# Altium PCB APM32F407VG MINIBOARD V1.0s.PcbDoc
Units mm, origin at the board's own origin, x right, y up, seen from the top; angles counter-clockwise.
Board outline 442.79 x 366.46 mm, 2 copper layers (Top Layer, Bottom Layer); 85 components, 122 nets, 428 pads, 246 vias.
Unrouted connection lines stored in the file: 122.
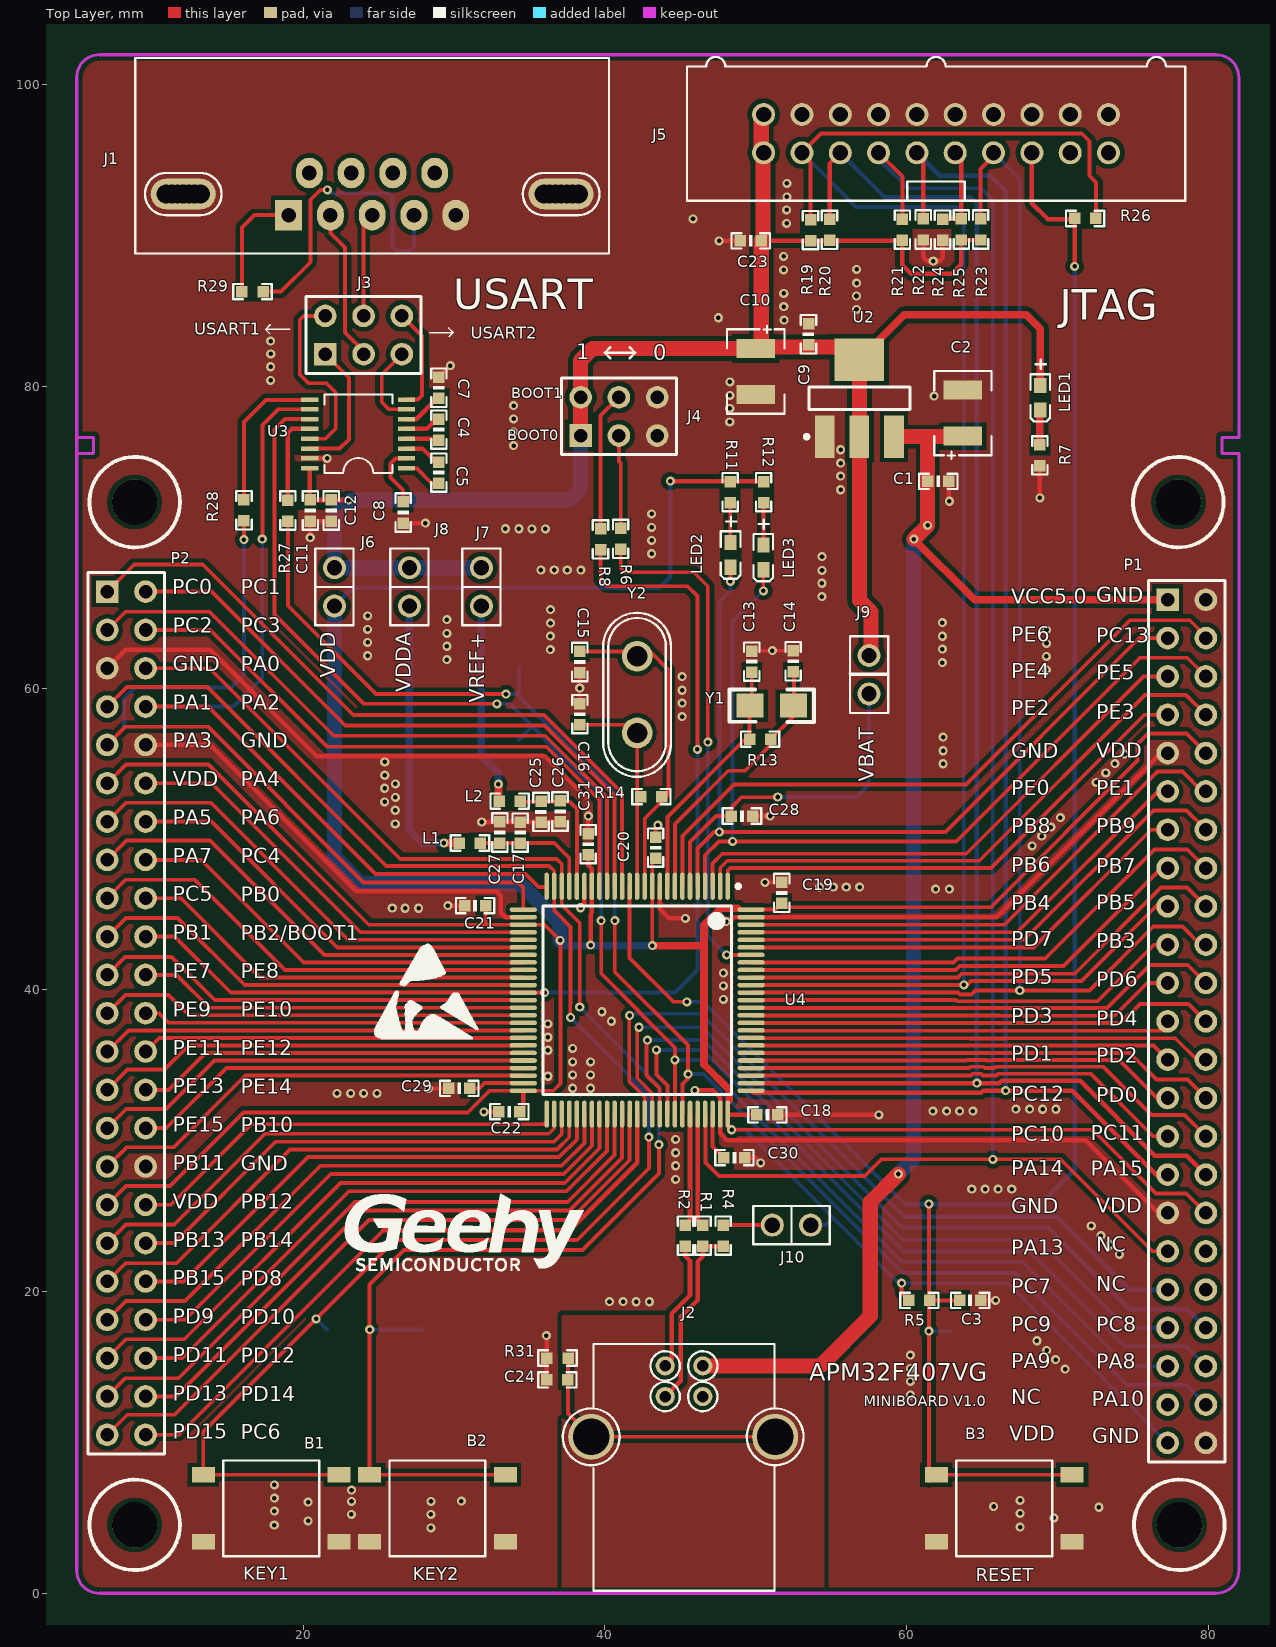
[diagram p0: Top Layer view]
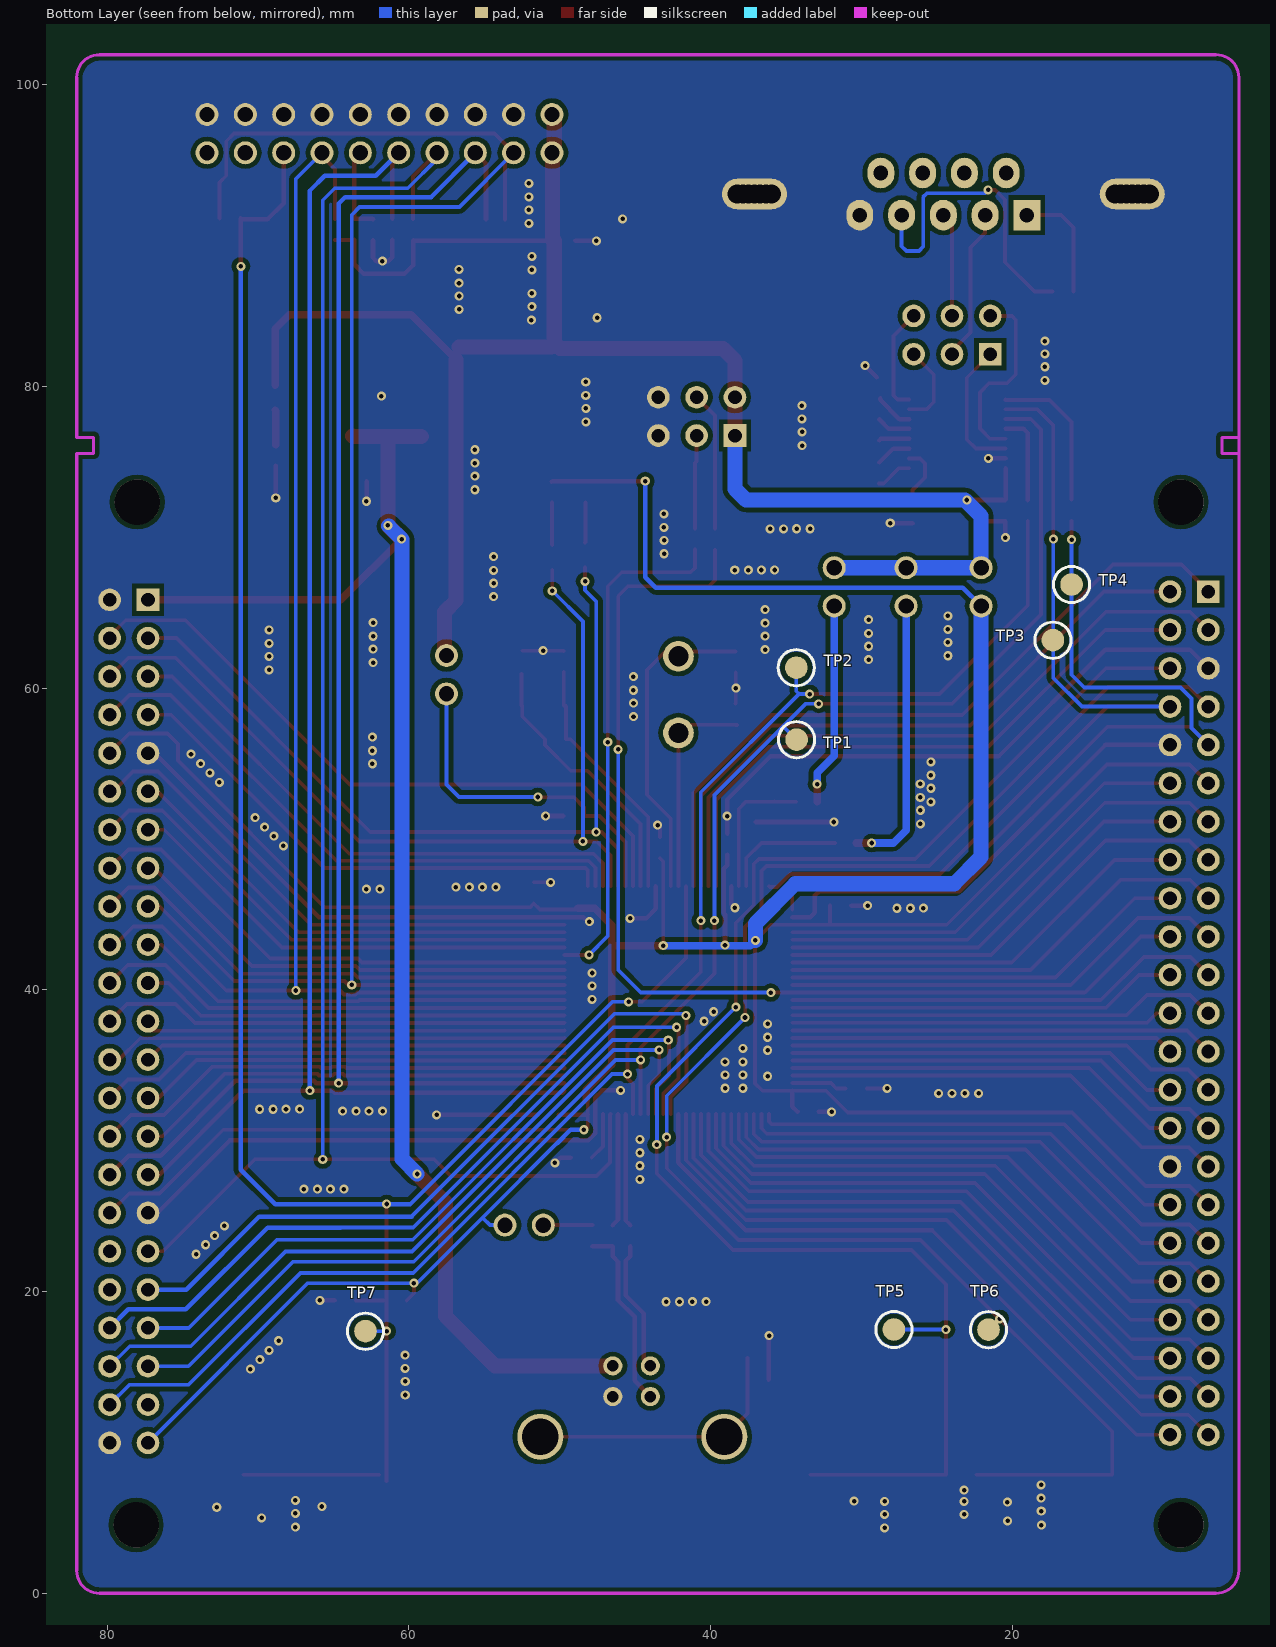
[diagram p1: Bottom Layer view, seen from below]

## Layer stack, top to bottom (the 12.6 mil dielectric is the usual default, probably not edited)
Top Layer: signal copper 0.0356
Dielectric: dielectric 0.32, FR-4, Dk 4.8
Bottom Layer: signal copper 0.0356

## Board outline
-118.26,-92.445 324.36,-92.445 324.36,273.475 323.99,273.845 323.82,274.015 -118.43,274.015

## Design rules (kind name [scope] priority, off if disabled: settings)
Clearance Clearance_1 [IsRegion] p1: gap=0.3
Clearance [All] p2: gap=0.2
ComponentClearance [All] p1: gap=0 collisioncheckmode=3 verticalgap=0.1 showdistances=FALSE
PolygonConnect [All] p1: connectstyle=Direct reliefconductorwidth=0.254 reliefentries=4 polygonreliefangle="45 Angle" airgapwidth=0.254
RoutingVias [All] p1: holewidth=0.3 width=0.6 viastyle="Through Hole" minholewidth=0.3 minwidth=0.6 maxholewidth=0.711 maxwidth=1.2
SilkToSolderMaskClearance SilkscreenOverComponentPads [IsPad] p1: minsilkscreentomaskgap=0.254 clearancetoexposedcopper=TRUE
SolderMaskExpansion [All] p1: expansion=0.102
Width Width_GND [InNet('GND')] p1: maxlimit=2 minlimit=0.15 preferedwidth=1
Width Width_C6-2 [InNet('NetC6_2')] p2: maxlimit=1.2 minlimit=1.2 preferedwidth=1.2
Width Width_MCU11 [InNet('MCU11')] p3: maxlimit=1.5 minlimit=0.3 preferedwidth=0.6
Width [All] p4: maxlimit=1 minlimit=0.254 preferedwidth=0.254 checkconnectedcopper=TRUE
26 further rules are at their usual default settings.

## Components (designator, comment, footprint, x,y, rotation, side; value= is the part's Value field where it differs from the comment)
B1 "Tamper" PB10 17.89,5.635 r90 top
B2 "Tamper" PB10 28.91,5.635 r90 top
B3 "Tamper" PB10 66.47,5.635 r90 top
C1 "100nF" 0603P 62.098,73.703 r180 top
C2 "220uF" TAN-B 63.73,78.22 r90 top
C3 "100nF" 0603P 64.21,19.415 r180 top
C4 "100nF" 0603P 29.003,74.282 r90 top
C5 "100nF" 0603P 29.003,77.132 r90 top
C7 "100nF" 0603P 29.003,79.904 r270 top
C8 "100nF" 0603P 26.634,71.635 r90 top
C9 "100nF" 0603P 53.5,83.45 r270 top
C10 "220uF" TAN-B 50,80.98 r270 top
C11 "100nF" 0603P 20.478,71.766 r270 top
C12 "100nF" 0603P 21.868,71.766 r90 top
C13 "10pF" 0603P 49.739,61.753 r270 top
C14 "10pF" 0603P 52.486,61.777 r270 top
C15 "20pF" 0603P 38.339,61.725 r90 top
C16 "20pF" 0603P 38.349,58.265 r270 top
C17 "10nF" 0603P 34.39,50.42 r270 top
C18 "100nF" 0603P 50.777,31.707 r180 top
C19 "100nF" 0603P 51.727,46.427 r270 top
C20 "100nF" 0603P 43.366,49.417 r270 top
C21 "100nF" 0603P 31.4,45.58 r0 top
C22 "100nF" 0603P 33.67,31.93 r0 top
C23 "100nF" 0603P 49.671,89.645 r0 top
C24 "4.7nF" 0603#1 36.153,14.155 r0 top
C25 "1uF" 0603P 35.771,51.791 r90 top
C26 "10nF" 0603P 37.031,51.821 r90 top
C27 "1uF" 0603P 33.04,50.428 r270 top
C28 "100nF" 0603P 49.091,51.52 r180 top
C29 "2.2uF" 0603P 30.351,33.47 r0 top (schematic designator C18)
C30 "2.2uF" 0603P 48.588,28.88 r180 top (schematic designator C18)
C31 "100nF" 0603P 38.9,49.649 r270 top (schematic designator C18)
J1 "DB9" DB9/F 19.046,91.345 r0 top
J2 "USB-typeB connector" USB-B 46.491,15.074 r0 top
J3 "Header 3X2" HDR2X3 21.471,82.127 r0 top (schematic designator P6)
J4 "Header 3X2" HDR2X3 38.394,76.735 r0 top (schematic designator P1)
J5 "JTAG" IDC20S 50.524,95.475 r90 top (schematic designator P4)
J6 "" SIP2 22.08,67.975 r270 top (schematic designator P9)
J7 "" SIP2 31.82,67.975 r270 top (schematic designator P10)
J8 "" SIP2 27.05,67.975 r270 top (schematic designator P8)
J9 "" SIP2 57.514,62.155 r270 top (schematic designator P2)
J10 "" SIP2 53.64,24.405 r180 top (schematic designator P7)
L1 "0R" 0603#1 31.76,49.73 r180 top
L2 "0R" 0603#1 34.387,52.5 r180 top
LED1 "LED" D0603 68.86,78.423 r90 top (schematic designator D1)
LED2 "LED" D0603 48.34,68.009 r90 top (schematic designator D2)
LED3 "LED" D0603 50.503,67.839 r90 top (schematic designator D3)
P1 "Header 25X2" HDR2X23 77.299,65.85 r270 top
P2 "Header 25X2" HDR2X23 7.02,66.39 r270 top
R1 "22R" 0603#2 46.505,23.712 r90 top
R2 "22R" 0603#2 45.346,23.712 r90 top
R4 "1.5K" 0603#2 47.846,23.712 r90 top
R5 "10K" 0603#2 60.841,19.415 r0 top
R6 "10K" 0603#2 41.053,69.887 r90 top
R7 "1.5K" 0603#2 68.83,75.42 r90 top
R8 "10K" 0603#2 39.715,69.855 r270 top
R11 "1.5K" 0603#2 50.523,72.986 r270 top
R12 "1.5K" 0603#2 48.31,72.986 r270 top
R13 "NC" 0603#2 50.29,56.61 r180 top
R14 "NC" 0603#2 43.08,52.8 r0 top
R19 "10K" 0603#2 53.634,90.355 r270 top
R20 "10K" 0603#2 54.894,90.375 r270 top
R21 "10K" 0603#2 59.724,90.385 r270 top
R22 "10K" 0603#2 61.104,90.395 r90 top
R23 "10K" 0603#2 64.904,90.395 r270 top
R24 "10K" 0603#2 62.384,90.385 r90 top
R25 "10K" 0603#2 63.634,90.395 r270 top
R26 "10K" 0603#2 71.84,91.125 r0 top
R27 "0R" 0603#2 18.994,71.765 r90 top
R28 "0R" 0603#2 16.084,71.785 r90 top
R29 "0R" 0603#2 16.65,86.275 r180 top
R31 "1M" 0603#2 36.861,15.595 r0 top (schematic designator R11)
TP1 "" TP1.5 34.31,56.58 r180 bottom
TP2 "" TP1.5 34.33,61.35 r180 bottom
TP3 "" TP1.5 17.32,63.175 r180 bottom
TP4 "" TP1.5 16.084,66.865 r180 bottom
TP5 "" TP1.5 27.86,17.485 r180 bottom
TP6 "" TP1.5 21.59,17.475 r180 bottom
TP7 "" TP1.5 62.883,17.375 r180 bottom
U2 "AMS1117" SPX1117M 56.87,79.21 r90 top
U3 "ST3232ECTR" TSSOP16 26.855,74.574 r180 top
U4 "APM32F407VG" LQFP100_N 42.146,39.314 r270 top
Y1 "32.768KHz" R1206 49.63,58.835 r0 top
Y2 "8MHz" XTAL_socket 42.14,59.565 r90 top

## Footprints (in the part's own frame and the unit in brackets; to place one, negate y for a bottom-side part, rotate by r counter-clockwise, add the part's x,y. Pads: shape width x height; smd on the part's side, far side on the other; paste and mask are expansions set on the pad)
0603#1 [mil]
  rect 30x30 smd: 1(0,0) 2(55,0)
  silkscreen extent -23,-20 77,20
0603#2 [mil]
  rect 30x30 smd: 1(-27.5,0) 2(27.5,0)
  silkscreen extent -50,-20 50,20
0603P [mil]
  rect 30x30 smd: 1(-27.5,0) 2(27.5,0)
  silkscreen extent -50,-20 50,20
D0603 [mm]
  rect 1x0.8 smd: 1(1.637,0) 2(0,0)
  silkscreen extent -0.76,-0.65 3.34,0.65
DB9/F [mil]
  round 50 hole 50: 0(-320,55) 0(-305,55) 0(-290,55) 0(-275,55) 0(-260,55) 0(-245,55) 0(-230,55) 0(666,55) 0(681,55) 0(696,55) 0(711,55) 0(726,55) 0(741,55) 0(756,55)
  oval 170x80 hole 50: 0(-275,55) 0(711,55)
  rect 70x80 hole 38: 1(0,0)
  oval 70x80 hole 38: 2(109,0) 3(218,0) 4(327,0) 5(436,0) 6(54,110) 7(163,110) 8(272,110) 9(381,110)
  silkscreen extent -400,-100 836,410
HDR2X3 [mm] "Connector; Header; 3x2 Position"
  rect 1.5x1.5 hole 0.9: 1(0,0)
  round 1.5 hole 0.9: 2(0,2.54) 3(2.54,0) 4(2.54,2.54) 5(5.08,0) 6(5.08,2.54)
  silkscreen extent -1.27,-1.27 6.35,3.81
HDR2X23 [mm] "Connector; Header; 25x2 Position"
  rect 1.5x1.5 hole 0.9: 1(0,0)
  round 1.5 hole 0.9: 2(0,2.54) 3(2.54,0) 4(2.54,2.54) 5(5.08,0) 6(5.08,2.54) 7(7.62,0) 8(7.62,2.54) 9(10.16,0) 10(10.16,2.54) 11(12.7,0) 12(12.7,2.54) 13(15.24,0) 14(15.24,2.54) 15(17.78,0) 16(17.78,2.54) 17(20.32,0) 18(20.32,2.54) 19(22.86,0) 20(22.86,2.54) 21(25.4,0) 22(25.4,2.54) 23(27.94,0) 24(27.94,2.54) 25(30.48,0) 26(30.48,2.54) 27(33.02,0) 28(33.02,2.54) 29(35.56,0) 30(35.56,2.54) 31(38.1,0) 32(38.1,2.54) 33(40.64,0) 34(40.64,2.54) 35(43.18,0) 36(43.18,2.54) 37(45.72,0) 38(45.72,2.54) 39(48.26,0) 40(48.26,2.54) 41(50.8,0) 42(50.8,2.54) 43(53.34,0) 44(53.34,2.54) 45(55.88,0) 46(55.88,2.54)
  silkscreen extent -1.27,-1.27 57.15,3.81
IDC20S [mil]
  round 60 hole 40: 1(0,0) 2(100,0) 3(0,-100) 4(100,-100) 5(0,-200) 6(100,-200) 7(0,-300) 8(100,-300) 9(0,-400) 10(100,-400) 11(0,-500) 12(100,-500) 13(0,-600) 14(100,-600) 15(0,-700) 16(100,-700) 17(0,-800) 18(100,-800) 19(0,-900) 20(100,-900)
  silkscreen extent -125,-1100 250,200
LQFP100_N [mm] "Thin QFP, 100-Leads, Body 14x14mm, Pitch 0.5mm, IPC Medium Density"
  oval 1.8x0.3 smd: 1(-7.55,6) 2(-7.55,5.5) 3(-7.55,5) 4(-7.55,4.5) 5(-7.55,4) 6(-7.55,3.5) 7(-7.55,3) 8(-7.55,2.5) 9(-7.55,2) 10(-7.55,1.5) 11(-7.55,1) 12(-7.55,0.5) 13(-7.55,0) 14(-7.55,-0.5) 15(-7.55,-1) 16(-7.55,-1.5) 17(-7.55,-2) 18(-7.55,-2.5) 19(-7.55,-3) 20(-7.55,-3.5) 21(-7.55,-4) 22(-7.55,-4.5) 23(-7.55,-5) 24(-7.55,-5.5) 25(-7.55,-6) 51(7.55,-6) 52(7.55,-5.5) 53(7.55,-5) 54(7.55,-4.5) 55(7.55,-4) 56(7.55,-3.5) 57(7.55,-3) 58(7.55,-2.5) 59(7.55,-2) 60(7.55,-1.5) 61(7.55,-1) 62(7.55,-0.5) 63(7.55,0) 64(7.55,0.5) 65(7.55,1) 66(7.55,1.5) 67(7.55,2) 68(7.55,2.5) 69(7.55,3) 70(7.55,3.5) 71(7.55,4) 72(7.55,4.5) 73(7.55,5) 74(7.55,5.5) 75(7.55,6)
  oval 0.3x1.8 smd: 26(-6,-7.55) 27(-5.5,-7.55) 28(-5,-7.55) 29(-4.5,-7.55) 30(-4,-7.55) 31(-3.5,-7.55) 32(-3,-7.55) 33(-2.5,-7.55) 34(-2,-7.55) 35(-1.5,-7.55) 36(-1,-7.55) 37(-0.5,-7.55) 38(0,-7.55) 39(0.5,-7.55) 40(1,-7.55) 41(1.5,-7.55) 42(2,-7.55) 43(2.5,-7.55) 44(3,-7.55) 45(3.5,-7.55) 46(4,-7.55) 47(4.5,-7.55) 48(5,-7.55) 49(5.5,-7.55) 50(6,-7.55) 76(6,7.55) 77(5.5,7.55) 78(5,7.55) 79(4.5,7.55) 80(4,7.55) 81(3.5,7.55) 82(3,7.55) 83(2.5,7.55) 84(2,7.55) 85(1.5,7.55) 86(1,7.55) 87(0.5,7.55) 88(0,7.55) 89(-0.5,7.55) 90(-1,7.55) 91(-1.5,7.55) 92(-2,7.55) 93(-2.5,7.55) 94(-3,7.55) 95(-3.5,7.55) 96(-4,7.55) 97(-4.5,7.55) 98(-5,7.55) 99(-5.5,7.55) 100(-6,7.55)
  silkscreen extent -7.67,-6.25 6.25,6.83, body extent -7,-7 7,7, height 1.6
PB10 [mil]
  rect 40x60 smd: 1(-87.5,177.17) 2(87.5,177.17) 3(87.5,-177.17) 4(-87.5,-177.17)
  silkscreen extent -125,-125 125,125
R1206 [mm]
  rect 1.8x1.6 smd: 1(0,0) 2(2.865,0)
  silkscreen extent -1.36,-1.08 4.24,1.08
SIP2 [mil]
  round 60 hole 40: 1(0,0) 2(100,0)
  silkscreen extent -50,-50 150,50
SPX1117M [mm]
  rect 2.8x1.3 smd: 1(-2.55,2.3) 2(-2.55,0) 3(-2.55,-2.3)
  rect 2.8x3.3 smd: 4(2.55,0)
  silkscreen extent -2.67,-3.35 0.75,3.62
TAN-B [mil]
  rect 50x100 smd: 1(-60,0) 2(60,0)
  silkscreen extent -120,-75 110,75
TP1.5 [mm]
  round 1.5 smd: 1(0,0)
  silkscreen extent -1.2,-1.2 1.2,1.2
TSSOP16 [mm]
  rect 1.15x0.3 smd: 1(0,0) 2(0,-0.65) 3(0,-1.3) 4(0,-1.95) 5(0,-2.6) 6(0,-3.25) 7(0,-3.9) 8(0,-4.55) 9(6.4,-4.55) 10(6.4,-3.9) 11(6.4,-3.25) 12(6.4,-2.6) 13(6.4,-1.95) 14(6.4,-1.3) 15(6.4,-0.65) 16(6.4,0)
  silkscreen extent 0.94,-4.88 5.42,0.33
USB-B [mil]
  round 120 hole 95: 0(-291,-185) 0(189,-185)
  round 50 hole 30: 1(0,0) 2(-98,0) 3(-98,-80) 4(0,-80)
  silkscreen extent -365,-586 263,57
XTAL_socket [mil]
  round 80 hole 53: 1(100,0) 2(-100,0)
  silkscreen extent -215,-89 214,89

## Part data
B1 B2 B3: library part "SW PUSHBUTTON", "SE PUSHBUTTON"
C1 C3 C9 C12 C13 C14 C15 C16 C17 C18 C19 C20 C21 C22 C23 C25 C26 C27 C28 C29 C30 C31: library part Cap, "Capacitor"
C2 C10: library part Cap2, "Capacitor"
C4 C5 C7 C8 C11 C24: library part CAP, "Capacitor"
J2: library part USB-B, "USB-B"
J3 J4: "Header, 3-Pin, Dual row"
J5: library part "Header 10X2", "Header, 10-Pin, Dual row"
J6 J7 J8 J9 J10: library part JP2
L1 L2: library part Inductor, "Inductor"
LED1 LED2 LED3: library part LED2, "Typical RED, GREEN, YELLOW, AMBER GaAs LED"
P1 P2: library part "Header 23X2", "Header, 25-Pin, Dual row"
R1 R2 R4 R5 R6 R7 R8 R11 R12 R13 R14 R19 R20 R21 R22 R23 R24 R25 R26 R27 R28 R29: library part Res2, "Resistor"
R31: library part RES, "'1/8W 5%"
TP1 TP2 TP3 TP4 TP5 TP6 TP7: library part TP
U2: library part SPX1117
U3: library part ST3232, "3.3V/5V Dual RS232 Transceiver w/ Int. Cap."
Y1: library part XTAL, "Crystal Oscillator"
Y2: library part CRYSTAL, "Crystal"

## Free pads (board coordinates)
  round 3 hole 3 paste+0 mask+0: 0(8.84,4.541) 0(8.84,72.32) 0(78.01,72.321) 0(78.079,4.54)

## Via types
v1: diameter 0.6, hole 0.3, Top Layer to Bottom Layer, 246 vias

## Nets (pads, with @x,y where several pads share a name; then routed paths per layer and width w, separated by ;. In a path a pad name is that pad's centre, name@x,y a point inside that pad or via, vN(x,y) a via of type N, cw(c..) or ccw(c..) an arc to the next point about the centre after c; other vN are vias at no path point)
+3.3V: C9.2 C10.1 C11.1 C12.2 C23.2 J4.1 J4.2 J5.1 J5.2 J6.1 J7.1 J8.1 J9.1 LED1.1 R19.2 R20.2 R21.2 R23.2 R25.2 U2.2 U2.4 U3.16 | length 132.8
  Top Layer w0.254: R25.2 R23.2
  Top Layer w0.3: U3.16 20.455,72.488 C11.1 C12.2 23.023,72.465 v1(23.024,72.463) ; C23.2 50.381,89.656 50.484,89.656 R19.2 59.694,89.656 R21.2 59.724,88.035 60.294,87.465 63.014,87.465 63.634,88.085 R25.2
  Top Layer w0.5: U2.4 59.84,84.73 67.93,84.73 68.86,83.8 LED1.1
  Top Layer w1: J4.1 J4.2 38.394,81.71 39.188,82.504 C10.1 50.37,82.874 C23.2 ; J5.1@50.37,95.475 50.37,97.86 J5.2 ; C23.2@50.484,89.656 50.484,95.434 J5.1 ; C10.1@50.55,82.6 U2.4@56.696,82.6 ; U2.4 U2.2 56.87,65.82 57.64,65.05 57.64,62.28 J9.1
  Bottom Layer w1: J7.1 J8.1 J6.1 22.08,71.4 23.143,72.463 37.658,72.463 38.394,73.199 J4.1
BOOT0: R6.1 U4.94 | length 34.1
  Top Layer w0.254: R6.1 41.053,67.966 41.34,67.68 45.894,67.68 46.824,66.75 v1(46.824,56.42) ; v1(48.066,42.317) 48.069,42.314 U4.94
  Bottom Layer w0.254: v1(46.824,56.42) 46.824,43.559 v1(48.066,42.317)
GND: B1.1 B1.4 B2.1 B2.4 B3.1 B3.4 C1.1 C2.2 C3.1 C7.1 C8.1 C9.1 C10.2 C11.2 C12.1 C13.1 C14.1 C15.1 C16.1 C17.1 C18.1 C19.1 C20.1 C21.1 C22.1 C23.1 C24.1 C25.1 C26.1 C27.1 C28.1 C29.1 C30.1 C31.1 J1.0 J1.5 J2.4 J4.5 J4.6 J5.4 J5.6 J5.8 J5.10 J5.12 J5.14 J5.16 J5.18 J5.20 P1.2 P1.9 P1.33 P1.46 P2.5 P2.10 P2.32 R7.1 R22.1 R24.1 R31.1 U2.1 U3.15 U4.10 U4.20 U4.27 U4.74 U4.99 | length 187.3
  Top Layer w0.254: v1(28.303,33.47) C29.1 ; C15.1 v1(38.339,60) 38.339,58.973 C16.1 ; C20.1 43.366,50.767 v1(43.516,50.917) ; C13.1 49.763,62.476 v1(51.106,62.476) C14.1 ; v1(50.616,47.117) 50.624,47.125 C19.1
  Top Layer w0.3: P2.5 8.24,62.53 13.86,62.53 20.896,55.495 36.015,55.495 38.9,52.61 C31.1 ; P2.10 13.84,56.23 23.53,46.54 32.81,46.54 33.1,46.25 33.1,45.11 33.396,44.814 U4.27 ; U3.15 v1(21.594,75.225) ; v1(20.478,69.969) C11.2 C12.1 ; C8.1@26.62,70.93 v1(28.101,70.93) ; C7.1 v1(29.767,81.366) ; v1(29.6,45.575) 29.61,45.575 29.616,45.58 C21.1 ; v1(31.843,51.123) C26.1 ; v1(31.99,31.91) C22.1@32.85,31.91 ; v1(36.13,17.085) 36.153,17.062 C24.1 ; v1(38.4,45.44) 38.646,45.686 U4.20 ; U4.10 43.646,45.364 44.28,44.73 v1(45.34,44.73) ; v1(45.967,33.33) 47.177,33.33 47.646,32.861 U4.74 47.646,30.487 48.116,30.017 71.869,30.017 76.676,25.21 P1.33 ; v1(47.58,89.645) C23.1 ; v1@48.101,44.464 48.451,44.814 U4.99 65.964,44.814 76.84,55.69 P1.9 ; C30.1 49.98,28.88 v1(50.33,28.53) ; C28.1 v1(50.95,51.52) v1@50.96,51.51 ; C18.1 v1(58.167,31.707) v1@58.17,31.71 ; R22.1 61.104,88.555 61.364,88.295 v1(61.769,88.295) 62.174,88.295 62.384,88.505 R24.1 ; C1.1 62.797,72.413 v1(62.83,72.38) ; C3.1 v1(65.9,19.415) ; v1@68.82,72.59 v1(68.83,72.6) R7.1
  other v1: 28.476,4.335 67.526,4.395 18.09,4.515 20.33,4.805 69.76,4.995 23.206,5.235 28.476,5.235 67.526,5.295 18.096,5.445 72.74,5.705 65.774,5.755 20.34,6.045 23.21,6.095 28.48,6.095 30.5,6.115 67.53,6.155 18.1,6.305 23.21,6.845 18.1,7.195 60.246,13.145 60.246,14.045 70.51,14.865 60.25,14.905 69.881,15.494 60.25,15.795 69.275,16.105 68.639,16.741 40.31,19.33 41.21,19.33 42.07,19.326 42.96,19.326 74.11,22.475 73.481,23.104 72.875,23.715 72.239,24.351 66.07,26.791 66.97,26.791 64.32,26.795 65.21,26.795 44.69,27.44 44.69,28.34 44.694,29.2 44.694,30.09 61.75,31.959 62.65,31.959 63.51,31.955 64.4,31.955 67.25,32.089 68.15,32.089 69.01,32.085 69.9,32.085 24.01,33.137 24.9,33.137 22.25,33.141 23.15,33.141 37.866,33.475 39.05,33.475 36.227,34.27 37.866,34.365 39.05,34.365 37.87,35.225 39.054,35.225 36.226,35.995 37.87,36.125 36.23,36.855 36.23,37.745 40.44,37.915 39.81,38.545 47.86,39.365 47.86,40.255 47.864,41.115 48.04,44.525 25.91,45.409 26.77,45.405 27.66,45.405 61.93,46.675 62.83,46.675 56,46.805 56.89,46.805 54.24,46.809 55.14,46.809 68.323,49.544 68.96,50.18 69.571,50.785 26.11,51 70.2,51.415 38.91,51.51 26.11,51.9 25.41,52.46 26.114,52.76 25.41,53.36 26.114,53.65 72.57,53.755 25.414,54.22 73.199,54.384 62.42,54.985 73.81,54.989 25.414,55.11 74.447,55.626 62.424,55.845 62.424,56.745 45.12,58.105 45.12,58.995 45.124,59.855 45.124,60.755 69.27,61.207 62.37,61.685 29.53,61.88 69.27,62.097 24.28,62.14 36.396,62.55 62.37,62.575 29.53,62.77 69.274,62.957 24.28,63.03 36.396,63.44 62.374,63.435 29.534,63.63 69.274,63.857 24.284,63.89 36.4,64.3 62.374,64.335 29.534,64.53 24.284,64.79 36.4,65.2 54.39,66.055 54.39,66.945 54.394,67.805 35.76,67.824 36.65,67.824 37.51,67.82 38.41,67.82 54.394,68.705 43.096,68.9 43.096,69.79 35.17,70.555 36.06,70.555 33.41,70.559 34.31,70.559 43.1,70.65 43.1,71.55 55.626,73.145 55.626,74.045 55.63,74.905 55.63,75.795 33.949,76.075 33.949,76.975 48.28,77.645 33.953,77.835 48.28,78.535 33.953,78.725 61.824,79.355 48.284,79.395 48.284,80.295 17.856,80.394 17.856,81.294 17.86,82.154 17.85,82.995 51.89,84.38 47.53,84.545 56.68,85.095 51.86,85.275 56.68,85.985 51.86,86.165 56.684,86.845 51.854,87.715 56.684,87.745 51.854,88.615 52.056,90.795 45.844,91.095 52.056,91.695 52.06,92.555 52.06,93.445
NC: P1.36
NetC4_1: C4.1 U3.1 | length 2.4
  Top Layer w0.254: U3.1 27.511,74.574 28.531,73.554 C4.1@28.837,73.554
NetC4_2: C4.2 U3.3 | length 2.4
  Top Layer w0.3: U3.3 27.914,75.874 C4.2@28.837,74.951
NetC5_1: C5.1 U3.4 | length 2
  Top Layer w0.3: U3.4 28.725,76.524 C5.1@28.837,76.412
NetC5_2: C5.2 U3.5 | length 2.2
  Top Layer w0.3: U3.5 28.202,77.174 C5.2@28.837,77.809
NetC7_2: C7.2 U3.6 | length 2.6
  Top Layer w0.3: U3.6 27.495,77.824 28.773,79.102 C7.2@28.773,79.206
NetC8_2: C8.2 U3.2 | length 4.3
  Top Layer w0.254: C8.2 26.634,73.125 25.794,73.965 25.794,74.894 26.124,75.224 U3.2 ; C8.2@26.916,72.473 27.074,72.473
NetC24_2: C24.2 J2.0 R31.2 | length 18
  Top Layer w0.254: R31.2 37.56,11.915 39.1,10.375 J2.0@51.292,10.375
NetC28_2: C28.2 J9.2 U4.6 | length 22.7
  Top Layer w0.254: U4.6 45.646,49.799 47.366,51.52 C28.2 48.393,52.093 49.06,52.76 51.45,52.76 51.46,52.77 v1(51.46,52.78)
  Bottom Layer w0.254: v1(51.46,52.78) 56.694,52.78 57.514,53.6 J9.2
NetC29_2: C29.2 U4.49 | length 3.7
  Top Layer w0.254: C29.2 31.68,33.47 32.024,33.814 U4.49
NetC30_2: C30.2 U4.73 | length 3.2
  Top Layer w0.254: U4.73 47.146,29.624 C30.2
NetJ1_1: J1.1 R29.2 | length 7.7
  Top Layer w0.254: R29.2 15.951,90.516 16.78,91.345 J1.1
NetJ1_4: J1.4 R29.1 | length 21
  Top Layer w0.254: R29.1 18.54,86.275 20.49,88.225 20.49,92.365 21.14,93.015 v1(21.61,93.015)
  Bottom Layer w0.254: v1(21.61,93.015) 21.829,92.796 25.659,92.796 25.92,92.535 25.92,89.245 26.2,88.965 27.03,88.965 27.351,89.286 J1.4
NetJ2_2: J2.2 R2.1 | length 8.7
  Top Layer w0.3: J2.2 44.43,15.501 44.43,18.545 45.646,19.761 45.646,22.049 45.346,22.349 R2.1
NetJ2_3: J2.3 R1.1 R4.1 | length 12.3
  Top Layer w0.3: J2.3 45.04,14.079 45.04,18.325 46.146,19.431 46.146,21.981 46.505,22.34 R1.1 R4.1
NetJ4_3: J4.3 R6.2 | length 6.2
  Top Layer w0.254: J4.3 40.934,75.025 41.053,74.906 R6.2
NetJ4_4: J4.4 R8.1 | length 9.2
  Top Layer w0.254: R8.1 39.715,78.054 J4.4
NetJ5_11: J5.11 R24.2 R25.1 | length 5.8
  Top Layer w0.3: R24.2 62.394,91.093 R25.1 63.634,95.065 J5.11
NetJ7_2: J7.2 L2.2 | length 13.5
  Top Layer w0.5: v1(32.95,53.64) 32.95,53.65 32.953,53.647 L2.2@32.953,52.47
  Bottom Layer w0.5: J7.2 31.82,55.51 32.95,54.38 v1(32.95,53.64)
NetJ8_2: J8.2 L1.2 | length 18.5
  Top Layer w0.5: v1(29.34,49.73) L1.2
  Bottom Layer w0.5: J8.2 27.05,50.59 27.91,49.73 v1(29.34,49.73)
NetJ10_2: J10.2 R4.2 | length 3.3
  Top Layer w0.254: R4.2 47.852,24.405 J10.2
NetLED1_2: LED1.2 R7.2 | length 2.3
  Top Layer w0.5: R7.2 68.83,78.393 LED1.2
NetLED2_1: LED2.1 R12.2 | length 2.7
  Top Layer w0.254: R12.2 48.31,69.676 LED2.1
NetLED3_1: LED3.1 R11.2 | length 2.8
  Top Layer w0.254: LED3.1 50.523,69.496 R11.2
NetR27_2: R27.2 U3.12 | length 6
  Top Layer w0.3: R27.2 18.994,76.904 19.264,77.174 U3.12
NetR28_2: R28.2 U3.9 | length 10.2
  Top Layer w0.254: R28.2 16.084,77.645 17.54,79.101 20.432,79.101 U3.9 U3.9@20.478,79.101
OSC8_IN: C15.2 R14.2 U4.12 Y2.1 | length 21.4
  Top Layer w0.254: C15.2 43.011,62.423 44.228,61.207 44.228,52.929 42.646,51.347 U4.12
OSC8_OUT: C16.2 R14.1 U4.13 Y2.2 | length 14.3
  Top Layer w0.254: C16.2@38.269,57.547 C16.2@38.349,57.547 ; C16.2 41.488,57.566 42.03,57.025 Y2.2 42.146,57.019 U4.13
PA0: B2.2 B2.3 P2.6 TP5.1 U4.23 | length 102.9
  Top Layer w0.254: P2.6@10.1,61.31 13.81,61.31 26.446,48.675 36.801,48.675 37.146,48.329 U4.23 37.146,45.629 38.339,44.436 v1(38.339,38.855) ; B2.3 B2.2 24.41,20.465 26.7,22.755 38.52,22.755 43.58,27.815 v1(43.58,29.745)
  Bottom Layer w0.254: v1(24.42,17.485) TP5.1 ; v1(38.339,38.855) 43.57,33.624 43.57,29.755 v1(43.58,29.745)
PA1: B1.2 B1.3 P2.7 TP6.1 U4.24 | length 107.2
  Top Layer w0.254: P2.7 8.32,60.07 13.66,60.07 25.516,48.215 36.31,48.215 36.646,47.879 U4.24 36.646,45.254 37.73,44.17 37.73,39.132 37.712,39.114 37.712,38.183 v1(37.73,38.165) ; B1.3 B1.2 13.39,10.715 26.1,23.425 38.17,23.425 42.92,28.175 v1(42.92,30.235)
  Bottom Layer w0.254: v1(20.86,18.195) 20.87,18.195 TP6.1 ; v1(37.73,38.165) 42.92,32.975 v1(42.92,30.235)
PA2: P2.8 TP3.1 U3.10 U4.25 | length 59.4
  Top Layer w0.254: P2.8@10.1,58.77 13.71,58.77 24.81,47.67 34.749,47.67 35.61,46.809 36.09,46.809 U4.25 ; v1(17.294,69.865) 17.304,69.875 17.304,77.445 18.333,78.474 U3.10
  Bottom Layer w0.254: P2.8@10.1,58.77 15.39,58.77 17.294,60.675 v1(17.294,69.865)
PA3: P2.9 R28.1 TP4.1 U4.26 | length 56.3
  Top Layer w0.254: P2.9 8.23,57.44 13.69,57.44 24.013,47.117 34.253,47.117 34.596,46.774 U4.26 ; v1(16.084,69.835) R28.1
  Bottom Layer w0.254: P2.9 8.134,57.345 8.134,59.315 8.864,60.045 15.244,60.045 16.084,60.885 TP4.1 v1(16.084,69.835)
PA4: P2.12 U4.29 | length 28.6
  Top Layer w0.254: P2.12@10.1,53.69 13.92,53.69 23.796,43.814 U4.29
PA5: P2.13 U4.30 | length 31.9
  Top Layer w0.254: P2.13 8.27,52.4 13.89,52.4 22.976,43.314 U4.30
PA6: P2.14 U4.31 | length 27.9
  Top Layer w0.254: P2.14@10.1,51.15 13.93,51.15 22.266,42.814 U4.31
PA7: P2.15 U4.32 | length 31.2
  Top Layer w0.254: P2.15 8.3,49.89 13.84,49.89 21.416,42.314 U4.32
PA8: P1.42 U4.67 | length 49.7
  Top Layer w0.254: v1(43.416,36.017) 43.416,34.377 44.146,33.647 U4.67
  Bottom Layer w0.254: v1(43.416,36.017) 46.453,36.017 59.81,22.66 68.184,22.66 74.464,16.38 78.509,16.38 P1.42
PA9: P1.41 TP1.1 U3.11 U4.68 | length 107
  Top Layer w0.254: U3.11 18.793,77.824 18.104,77.135 18.104,64.88 24.03,58.955 v1(32.85,58.955) ; v1(39.76,44.59) 39.76,41.07 42.273,38.557 42.273,38.537 44.646,36.164 v1(44.646,35.352) 44.646,32.955 U4.68
  Bottom Layer w0.254: v1@32.84,58.945 v1(32.85,58.955) 33.72,58.955 35.212,57.462 ; TP1.1 35.192,57.462 35.212,57.462 ; v1(39.76,44.59) 39.76,52.915 35.212,57.462 ; v1(44.646,35.352) 46.315,35.352 59.687,21.98 67.694,21.98 74.624,15.05 P1.41
PA10: P1.44 R27.1 TP2.1 U4.69 | length 101.1
  Top Layer w0.254: R27.1 18.994,65.45 24.84,59.605 v1(33.45,59.605) ; v1(40.66,44.58) 40.66,41.19 45.516,36.334 v1(45.516,34.417) 45.516,34.117 45.146,33.747 U4.69
  Bottom Layer w0.254: v1(33.45,59.605) 34.15,59.605 ; TP2.1 34.33,59.785 34.15,59.605 ; v1(40.66,44.58) 40.66,53.095 34.15,59.605 ; v1(45.516,34.417) 46.543,34.417 59.72,21.24 67.194,21.24 74.61,13.825 78.525,13.825 P1.44
PA11: R2.2 U4.70 | length 7.5
  Top Layer w0.3: R2.2 45.646,24.71 U4.70
PA12: R1.2 U4.71 | length 7.5
  Top Layer w0.3: U4.71 46.146,24.769 R1.2
PA13: J5.7 P1.35 R21.1 U4.72 | length 115
  Top Layer w0.254: U4.72 46.669,31.741 46.669,28.551 47.57,27.65 57.23,27.65 58.347,28.767 70.212,28.767 76.309,22.67 P1.35 ; J5.7 59.724,93.895 R21.1
  Bottom Layer w0.254: J5.7 58.144,95.065 60.084,93.125 64.924,93.125 65.714,92.335 v1(65.714,28.755)
PA14: J5.9 P1.31 R22.2 U4.76 | length 101.2
  Top Layer w0.3: U4.76 49.846,33.165 64.934,33.165 65.083,33.314 70.975,33.314 76.539,27.75 P1.31 ; J5.9 61.104,95.055 R22.2
  Bottom Layer w0.3: J5.9 62.194,93.965 65.574,93.965 66.564,92.975 v1(66.564,33.315)
PA15: J5.5 P1.32 R20.1 U4.77 | length 106.2
  Top Layer w0.3: U4.77 66.145,33.814 66.295,33.965 71.505,33.965 76.459,29.01 78.579,29.01 P1.32 ; R20.1 54.894,94.765 J5.5
  Bottom Layer w0.3: J5.5 58.534,92.545 64.234,92.545 64.664,92.115 v1(64.664,33.815)
PB0: P2.18 U4.35 | length 27.2
  Top Layer w0.254: P2.18 11.9,46.07 17.156,40.814 U4.35
PB1: P2.19 U4.36 | length 29.9
  Top Layer w0.254: P2.19 8.26,44.77 11.68,44.77 16.136,40.314 U4.36
PB2: P2.20 R8.2 U4.37 | length 72.5
  Top Layer w0.254: P2.20 11.49,43.53 15.206,39.814 U4.37 v1(36.013,39.814) ; R8.2 39.715,67.145 40.11,66.75 45.474,66.75 46.134,66.09 v1(46.134,55.935)
  Bottom Layer w0.254: v1(36.013,39.814) 44.64,39.814 46.134,41.309 v1(46.134,55.935) v1@46.134,56.03
PB3: J5.13 P1.20 R23.1 U4.89 | length 93.5
  Top Layer w0.254: U4.89 63.418,39.814 63.535,39.698 64.303,39.698 64.56,39.955 v1(67.5,39.955) 72.113,39.955 76.349,44.19 78.279,44.19 79.479,42.99 P1.20 ; R23.1 64.904,94.405 65.764,95.265 J5.13
  Bottom Layer w0.254: J5.13 67.5,93.739 v1(67.5,39.955)
PB4: J5.3 P1.17 R19.1 R26.2 U4.90 | length 123.6
  Top Layer w0.254: U4.90 v1@63.794,40.314 ; J5.3@53.041,95.452 54.334,96.745 71.606,96.745 72.114,96.237 72.114,93.951 72.559,93.506 R26.2@72.559,91.155 ; J5.3 53.064,95.429 53.634,94.859 R19.1 ; v1(63.794,40.325) 64.01,40.325 64.267,40.582 71.583,40.582 P1.17@76.569,45.567 ; R26.2 72.539,91.718 ; P1.17@76.569,45.53 P1.17
  Bottom Layer w0.254: J5.3 56.654,91.885 63.274,91.885 63.794,91.365 v1(63.794,40.325)
PB5: P1.18 U4.91 | length 33.1
  Top Layer w0.254: U4.91 63.397,40.814 63.648,41.065 71.143,41.065 76.859,46.78 78.589,46.78 P1.18
PB6: P1.15 U4.92 | length 30.4
  Top Layer w0.254: U4.92 63.255,41.314 63.526,41.585 70.403,41.585 76.889,48.07 P1.15
PB7: P1.16 U4.93 | length 33.8
  Top Layer w0.254: U4.93 63.113,41.814 63.374,42.075 69.193,42.075 76.429,49.31 78.599,49.31 P1.16
PB8: P1.13 U4.95 | length 30.8
  Top Layer w0.254: U4.95 68.423,42.814 76.219,50.61 P1.13
PB9: P1.14 U4.96 | length 34.2
  Top Layer w0.254: U4.96 67.78,43.314 76.356,51.89 78.559,51.89 P1.14
PB10: P2.30 U4.47 | length 26.7
  Top Layer w0.254: P2.30 10.93,30.83 14.914,34.814 U4.47
PB11: P2.31 U4.48 | length 30.1
  Top Layer w0.254: P2.31 8.29,29.56 11.41,29.56 16.164,34.314 U4.48
PB12: P2.34 U4.51 | length 29.4
  Top Layer w0.254: P2.34 11.24,25.75 16.584,31.095 35.98,31.095 36.146,31.261 U4.51
PB13: P2.35 U4.52 | length 33.7
  Top Layer w0.254: P2.35 8.26,24.45 11.46,24.45 17.474,30.465 36.286,30.465 36.646,30.825 U4.52
PB14: P2.36 U4.53 | length 31.9
  Top Layer w0.254: P2.36 11.47,23.21 18.194,29.935 36.646,29.935 37.146,30.435 U4.53
PB15: P2.37 U4.54 | length 36.1
  Top Layer w0.254: P2.37 8.23,21.88 11.61,21.88 19.144,29.415 36.828,29.415 37.646,30.233 U4.54
PC0: P2.1 U4.15 | length 47.3
  Top Layer w0.254: P2.1 8.81,68.18 13.35,68.18 23.326,58.205 35.975,58.205 41.146,53.034 U4.15
PC1: P2.2 U4.16 | length 42.2
  Top Layer w0.254: P2.2@10.1,66.39 13.93,66.39 22.796,57.525 36.007,57.525 40.646,52.886 U4.16
PC2: P2.3 U4.17 | length 44.6
  Top Layer w0.254: P2.3 8.23,65.06 13.81,65.06 22.036,56.835 36.055,56.835 40.146,52.744 U4.17
PC3: P2.4 U4.18 | length 39.9
  Top Layer w0.254: P2.4@10.1,63.85 13.85,63.85 21.586,56.115 36.115,56.115 39.646,52.584 U4.18
PC4: P2.16 U4.33 | length 27.3
  Top Layer w0.254: P2.16@10.1,48.61 13.25,48.61 20.046,41.814 U4.33
PC5: P2.17 U4.34 | length 30.6
  Top Layer w0.254: P2.17 8.25,47.3 12.81,47.3 18.796,41.314 U4.34
PC6: P2.46 U4.63 | length 43.3
  Top Layer w0.254: P2.46 11.77,10.51 25.324,24.065
  Top Layer w0.3: 25.324,24.065 37.683,24.065 42.146,28.527 U4.63
PC7: P1.37 U4.64 | length 50.2
  Top Layer w0.254: v1(41.646,38.297) 41.616,38.267 41.616,33.917 42.646,32.887 U4.64
  Bottom Layer w0.254: v1(41.646,38.297) 41.766,38.417 46.377,38.417 59.823,24.971
  Bottom Layer w0.3: 59.823,24.971 69.913,24.971 74.754,20.13 P1.37
PC8: P1.40 U4.65 | length 52
  Top Layer w0.254: v1(42.266,37.517) 42.146,37.397 42.146,34.137 43.146,33.137 U4.65
  Bottom Layer w0.254: v1(42.266,37.517) 46.44,37.517 59.717,24.24 64.52,24.24
  Bottom Layer w0.3: 64.52,24.24 69.374,24.24 74.784,18.83 78.599,18.83 P1.40
PC9: P1.39 U4.66 | length 47.7
  Top Layer w0.254: v1(42.816,36.667) 42.766,36.617 42.766,34.32 43.646,33.44 U4.66
  Bottom Layer w0.254: v1(42.816,36.667) 46.51,36.667 59.747,23.43 68.754,23.43 74.594,17.59 P1.39
PC10: P1.29 U4.78 | length 29.5
  Top Layer w0.254: U4.78@49.719,34.291 U4.78 64.277,34.314 64.405,34.442 64.924,34.442 65.051,34.314 65.97,34.314 66.098,34.442 72.188,34.442 76.339,30.29 P1.29
PC11: P1.30 U4.79 | length 32.2
  Top Layer w0.254: U4.79@49.719,34.791 U4.79 64.135,34.814 64.217,34.896 65.112,34.896 65.193,34.814 65.828,34.814 65.909,34.896 73.054,34.896 76.239,31.71 78.419,31.71 P1.30
PC12: P1.27 U4.80 | length 28.7
  Top Layer w0.254: U4.80@49.719,35.291 U4.80 63.993,35.314 64.029,35.35 65.3,35.35 65.336,35.314 65.686,35.314 65.721,35.35 74.08,35.35 76.599,32.83 P1.27
PC13: P1.4 U4.7 | length 44.5
  Top Layer w0.254: U4.7 45.146,50.186 48.569,53.61 63.929,53.61 74.81,64.49 78.769,64.49 79.839,63.42 P1.4
PC14: C14.2 R13.1 U4.8 Y1.2 | length 18
  Top Layer w0.254: U4.8 44.646,50.986 48.179,54.52 49.28,54.52 50.988,56.228 R13.1 52.495,58.116 Y1.2 ; Y1.2@52.533,58.835 C14.2@52.533,60.928
PC15: C13.2 R13.2 U4.9 Y1.1 | length 16.6
  Top Layer w0.254: U4.9 44.146,51.456 49.299,56.61 R13.2 49.591,58.796 Y1.1 ; Y1.1@49.739,58.835 C13.2
PC_RX: J1.3 J3.4 | length 6.9
  Top Layer w0.254: J3.4 24.011,90.773 J1.3
PC_TX: J1.2 J3.3 | length 10.1
  Top Layer w0.254: J1.2 21.814,90.16 22.784,89.19 22.784,83.565 24.011,82.338 J3.3
PD0: P1.28 U4.81 | length 31.4
  Top Layer w0.254: U4.81@49.719,35.791 U4.81 74.795,35.814 76.559,34.05 78.619,34.05 P1.28
PD1: P1.25 U4.82 | length 28
  Top Layer w0.254: U4.82@49.719,36.291 U4.82 76.355,36.314 P1.25
PD2: P1.26 U4.83 | length 33.2
  Top Layer w0.254: U4.83 49.719,36.791 64.176,36.791 ; 66.614,36.794 66.611,36.791 ; P1.26 79.229,35.37 77.808,36.791 66.611,36.791 ; 64.176,36.791 64.194,36.773 66.593,36.773 66.611,36.791 ; 64.176,36.791 66.611,36.791
PD3: P1.23 U4.84 | length 28.2
  Top Layer w0.254: U4.84 49.719,37.291 66.469,37.291 ; 66.472,37.294 66.469,37.291 ; P1.23@77.051,37.291 76.68,37.291 ; P1.23 76.68,37.291 ; 66.469,37.291 76.68,37.291
PD4: P1.24 U4.85 | length 33
  Top Layer w0.254: U4.85 49.719,37.791 64.454,37.791 ; 66.33,37.794 64.457,37.794 64.454,37.791 ; P1.24 78.679,39.07 75.469,39.07 74.19,37.791 64.454,37.791
PD5: P1.21 U4.86 | length 34.8
  Top Layer w0.254: U4.86 49.719,38.291 64.596,38.291 64.599,38.294 66.188,38.294 ; 59.907,38.285 66.194,38.285 ; 66.188,38.291 66.194,38.285 ; P1.21 75.949,40.45 73.784,38.285 66.194,38.285
PD6: P1.22 U4.87 | length 31.8
  Top Layer w0.254: U4.87 49.716,38.794 63.154,38.794 63.159,38.79 73.278,38.79 76.139,41.65 78.639,41.65 P1.22
PD7: P1.19 U4.88 | length 29.2
  Top Layer w0.254: U4.88 63.276,39.314 63.347,39.244 72.652,39.244 76.399,42.99 P1.19
PD8: P2.38 U4.55 | length 34.2
  Top Layer w0.254: P2.38 12.08,20.67 20.324,28.915 36.97,28.915 38.146,30.091 U4.55
PD9: P2.39 U4.56 | length 38.4
  Top Layer w0.254: P2.39 8.26,19.37 12.18,19.37 21.144,28.335 37.13,28.335 38.646,29.851 U4.56
PD10: P2.40 U4.57 | length 36.5
  Top Layer w0.254: P2.40 12.17,18.13 21.834,27.795 37.28,27.795 39.146,29.661 U4.57
PD11: P2.41 U4.58 | length 40.7
  Top Layer w0.254: P2.41 8.27,16.84 12.13,16.84 22.484,27.195 37.34,27.195 39.646,29.501 U4.58
PD12: P2.42 U4.59 | length 38.7
  Top Layer w0.254: P2.42 11.99,15.59 23.044,26.645 37.47,26.645 40.146,29.321 U4.59
PD13: P2.43 U4.60 | length 43
  Top Layer w0.254: P2.43 8.23,14.26 11.76,14.26 23.444,25.945 37.54,25.945 40.646,29.051 U4.60
PD14: P2.44 U4.61 | length 41
  Top Layer w0.254: P2.44 11.59,13.05 23.904,25.365 37.667,25.365 41.146,28.844 U4.61
PD15: P2.45 U4.62 | length 45.2
  Top Layer w0.254: P2.45 8.35,11.84 11.47,11.84 24.364,24.735 37.679,24.735 41.646,28.702 U4.62
PE0: P1.11 U4.97 | length 31.5
  Top Layer w0.254: U4.97 67.323,43.814 76.659,53.15 P1.11
PE1: P1.12 U4.98 | length 34.9
  Top Layer w0.254: U4.98 66.489,44.314 76.635,54.46 78.289,54.46 79.599,53.15 P1.12
PE2: P1.7 U4.1 | length 34.5
  Top Layer w0.254: U4.1 48.146,47.899 48.311,48.065 65.604,48.065 75.77,58.23 P1.7
PE3: P1.8 U4.2 | length 38.7
  Top Layer w0.254: U4.2 47.646,48.09 48.11,48.555 64.814,48.555 75.81,59.55 78.519,59.55 P1.8
PE4: P1.5 U4.3 | length 36.8
  Top Layer w0.254: U4.3 47.146,48.38 47.78,49.015 63.954,49.015 75.71,60.77 P1.5
PE5: LED3.2 P1.6 U4.4 | length 60
  Top Layer w0.254: U4.4 46.646,48.92 47.559,49.833 v1(48.47,49.833) 63.293,49.833 75.47,62.01 78.599,62.01 P1.6 ; v1(50.503,66.445) 50.503,66.465 LED3.2
  Bottom Layer w0.254: v1(48.47,49.833) 48.47,64.412 v1(50.503,66.445)
PE6: LED2.2 P1.3 U4.5 | length 57.3
  Top Layer w0.254: U4.5 46.146,49.369 47.237,50.46 v1(47.59,50.46) 62.57,50.46 75.42,63.31 P1.3 ; v1(48.323,67.075) 48.343,67.075 48.34,67.078 LED2.2
  Bottom Layer w0.254: v1(47.59,50.46) 47.59,65.745 48.323,66.478 v1(48.323,67.075)
PE7: P2.21 U4.38 | length 29.3
  Top Layer w0.254: P2.21 8.21,42.18 11.28,42.18 14.146,39.314 U4.38
PE8: P2.22 U4.39 | length 25.9
  Top Layer w0.254: P2.22 11.62,40.99 13.796,38.814 U4.39
PE9: P2.23 U4.40 | length 28.6
  Top Layer w0.254: P2.23 8.23,39.66 11.09,39.66 12.436,38.314 U4.40
PE10: P2.24 U4.41 | length 25.3
  Top Layer w0.254: P2.24 10.45,38.45 11.086,37.814 U4.41
PE11: P2.25 U4.42 | length 28.2
  Top Layer w0.254: P2.25 8.424,37.314 U4.42
PE12: P2.26 U4.43 | length 25.4
  Top Layer w0.254: P2.26 10.464,36.814 U4.43
PE13: P2.27 U4.44 | length 28.8
  Top Layer w0.254: P2.27 8.36,34.71 10.82,34.71 12.424,36.314 U4.44
PE14: P2.28 U4.45 | length 26
  Top Layer w0.254: P2.28 11.09,33.37 13.534,35.814 U4.45
PE15: P2.29 U4.46 | length 29.4
  Top Layer w0.254: P2.29 8.28,32.09 10.91,32.09 14.134,35.314 U4.46
RESET: B3.2 B3.3 C3.2 J5.15 R5.2 R26.1 TP7.1 U4.14 | length 142.4
  Top Layer w0.254: U4.14 41.646,42.114 44.556,39.205 v1(45.44,39.205) ; B3.2@61.483,7.435 v1(61.483,17.375) v1(61.483,25.805) ; R5.2 C3.2 ; B3.2 B3.3
  Top Layer w0.3: J5.15 68.304,92.139 69.36,91.083 71.1,91.083 R26.1 v1(71.142,87.952)
  Bottom Layer w0.254: v1(45.44,39.205) 46.513,39.205 59.937,25.78 ; v1(61.483,17.375) TP7.1
  Bottom Layer w0.3: 59.937,25.78 68.86,25.78 71.152,28.072 71.152,87.942 v1(71.142,87.952)
U1_RX: J3.2 U3.13 | length 12.7
  Top Layer w0.254: U3.13 21.493,76.524 22.164,77.195 22.164,79.595 21.554,80.205 20.364,80.205 19.78,80.789 19.78,84.405 20.042,84.667 J3.2 J3.2@21.443,84.695
U1_TX: J3.1 U3.14 | length 9.2
  Top Layer w0.254: U3.14 22.423,75.874 23.034,76.485 23.034,80.563 J3.1
  Bottom Layer w0.254: J3.1@21.383,82.215 J3.1
U2_RX: J3.6 U3.8 | length 7
  Top Layer w0.254: J3.6 27.884,83.333 27.884,79.387 27.621,79.124 U3.8
U2_TX: J3.5 U3.7 | length 5.6
  Top Layer w0.254: J3.5 25.217,80.793 25.217,78.952 25.695,78.474 U3.7
VCC5.0: C1.2 C2.1 J2.1 P1.1 U2.3 | length 97
  Top Layer w0.5: v1(60.49,69.87) 64.509,65.85 P1.1 P1.1@77.67,65.85
  Top Layer w1: J2.1 54.289,15.074 57.59,18.375 57.59,25.92 v1(59.462,27.792) ; U2.3 61.32,76.66 ; v1(60.49,69.87) v1(61.4,70.78) C1.2 61.4,76.58 61.32,76.66 ; C2.1 63.694,76.66 61.32,76.66
  Bottom Layer w1: v1(59.462,27.792) 60.45,28.78 60.45,69.84 v1@61.34,70.73
VDD: C18.2 C19.2 C20.2 C21.2 C22.2 C31.2 J6.2 J10.1 P1.10 P1.34 P1.45 P2.11 P2.33 R5.1 R11.1 R12.1 U4.11 U4.19 U4.28 U4.50 U4.75 U4.100 | length 304.6
  Top Layer w0.254: P2.33 8.274,27.005 11.18,27.005 16.05,31.875 30.915,31.875 32.354,33.314 U4.50 36.58,33.314 37.06,33.795 v1@37.06,43.264 ; P2.11 8.26,54.93 13.74,54.93 24.356,44.314 32.091,44.314 ; C21.2 32.098,44.322 32.091,44.314 ; v1@37.047,43.277 36.009,44.314 U4.28 32.091,44.314 ; v1(43.146,42.93) U4.11 43.146,48.499 C20.2 ; 46.593,42.93 46.593,44.307 ; 48.146,32.685 U4.75 48.146,30.887 v1@48.359,30.675 ; v1(48.409,30.725) 72.314,30.725 76.529,26.51 78.539,26.51 P1.34 ; U4.100@48.8,45.314 U4.100 51.313,45.314 C19.2 51.988,45.467 65.583,45.467 75.31,55.195 75.31,56.285 76.01,56.985 78.545,56.985 P1.10 ; v1(59.67,20.555) 59.67,19.888 R5.1
  Top Layer w0.3: C22.2@34.247,31.91 34.596,32.259 U4.50 ; C31.2 38.9,48.26 39.146,48.014 U4.19 39.146,45.096 39.054,45.004 v1(39.054,42.96) ; v1@38.94,42.92 v1@38.94,42.96 ; v1(44.34,73.71) 50.498,73.71 R11.1 ; U4.75 48.203,31.707 C18.2
  Top Layer w0.5: v1(43.146,42.93) 46.573,42.93 ; 48.246,32.685 48.246,33.378 46.573,35.05 46.573,42.93 ; 48.8,45.414 47.701,45.414 46.593,44.307 46.573,44.287 46.573,42.93
  Bottom Layer w0.254: 50.178,29.837 55.125,24.89 ; J10.1 54.64,24.405 55.125,24.89 ; v1@59.464,20.55 55.125,24.89 ; v1@59.67,20.55 66.719,20.55 P1.45
  Bottom Layer w0.3: J6.2 23.295,66.65 43.64,66.65 44.34,67.35 v1(44.34,73.71) ; v1(48.409,30.725) 49.29,30.725 50.178,29.837
  Bottom Layer w0.5: v1(37.04,43.27) 37.38,42.93 v1(43.146,42.93)
  Bottom Layer w1: J6.2 22.08,48.81 23.86,47.03 34.401,47.03 37.04,44.39 v1(37.04,43.27)
VDDA: C17.2 C27.2 L1.1 U4.22 | length 8.2
  Top Layer w0.254: L1.1 C27.2 36.645,49.73 37.646,48.729 U4.22
VREF+: C25.2 C26.2 L2.1 U4.21 | length 9.1
  Top Layer w0.254: L2.1@34.35,52.47 37.67,52.47 38.146,51.994 U4.21 ; C25.2 C25.2@35.781,52.5
pads on no net: J1.6 J1.7 J1.8 J1.9 J5.17 J5.19 P1.38 P1.43

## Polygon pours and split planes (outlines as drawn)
GND on Bottom Layer "Bottom Layer-No Net" (solid, pour order 8): 4.588,101.932 4.588,-0.042 81.608,-0.042 81.608,101.932 4.588,101.932
GND on Top Layer "Bottom Layer-No Net" (solid, remove dead copper, pour order 12): 4.792,102.125 4.792,0.151 81.812,0.151 81.812,102.125 4.792,102.125
NetC24_2 on Top Layer "Bottom Layer-No Net" (solid, remove dead copper, pour order 10): 54.53,-0.035 54.53,17.815 54.53,17.935 54.15,18.315 54.02,18.445 37.15,18.445 37.15,-0.005 37.2,-0.055 37.22,-0.035 54.53,-0.035

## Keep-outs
Keep-Out Layer:
  lines w0.2: 5,75.56 6.12,75.56 6.12,76.62 5,76.62 ; 82.01,75.56 80.9,75.56 80.9,76.62 82.02,76.62 82.02,100.475 ccw(c80.52,100.475) 80.52,101.975 6.5,101.975 ccw(c6.5,100.475) 5,100.475 5,1.505 ccw(c6.5,1.505) 6.5,0.005 80.52,0.005 ccw(c80.52,1.505) 82.02,1.505 82.02,75.55

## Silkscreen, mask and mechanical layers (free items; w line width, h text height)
Top Overlay:
  drawing of 4746 lines, arcs and shapes, not listed
  text "USART" at 29.96,85.115 h2
  text "JTAG" at 70.16,84.415 h2
  text "USART1" at 12.79,83.425 h0.8
  text "USART2" at 31.11,83.155 h0.8
  text "1" at 38.1,81.785 h1.02
  text "0" at 43.22,81.725 h1.02
  text "BOOT1" at 33.81,79.215 h0.7
  text "BOOT0" at 33.54,76.425 h0.7
  text "PC0" at 11.33,65.88 h1.7
  text "PC1" at 15.86,65.88 h1.7
  text "GND" at 72.58,65.345 h1.7
  text "GND" at 72.58,65.345 h1.7
  text "VCC5.0" at 66.93,65.245 h1.7
  text "PC2" at 11.36,63.335 h1.7
  text "PC3" at 15.86,63.334 h1.7
  text "PE6" at 66.93,62.75 h1.7
  text "PC13" at 72.58,62.658 h1.7
  text "GND" at 11.36,60.791 h1.7
  text "PA0" at 15.86,60.788 h1.7
  text "VDD" at 22.48,60.67 h1.7 r90
  text "PE4" at 66.93,60.32 h1.7
  text "PE5" at 72.58,60.21 h1.7
  text "VDDA" at 27.46,59.73 h1.7 r90
  text "VREF+" at 32.35,59.03 h1.7 r90
  text "PA1" at 11.36,58.246 h1.7
  text "PA2" at 15.86,58.242 h1.7
  text "PE2" at 66.93,57.85 h1.7
  text "PE3" at 72.58,57.6 h1.7
  text "PA3" at 11.36,55.701 h1.7
  text "GND" at 15.86,55.696 h1.7
  text "VDD" at 72.58,55.04 h1.7
  text "GND" at 66.93,55.03 h1.7
  text "VBAT" at 58.144,53.78 h1.7 r90
  text "VDD" at 11.36,53.157 h1.7
  text "PA4" at 15.86,53.15 h1.7
  text "PE0" at 66.93,52.55 h1.7
  text "PE1" at 72.58,52.56 h1.7
  text "PA5" at 11.36,50.612 h1.7
  text "PA6" at 15.86,50.604 h1.7
  text "PB8" at 66.93,50.05 h1.7
  text "PB9" at 72.58,50.05 h1.7
  text "PA7" at 11.36,48.068 h1.7
  text "PC4" at 15.86,48.058 h1.7
  text "PB6" at 66.93,47.46 h1.7
  text "PB7" at 72.58,47.39 h1.7
  text "PC5" at 11.36,45.523 h1.7
  text "PB0" at 15.86,45.512 h1.7
  text "PB5" at 72.58,44.97 h1.7
  text "PB4" at 66.93,44.95 h1.7
  text "PB1" at 11.36,42.979 h1.7
  text "PB2/BOOT1" at 15.86,42.966 h1.7
  text "PD7" at 66.93,42.57 h1.7
  text "PB3" at 72.58,42.43 h1.7
  text "PE7" at 11.36,40.434 h1.7
  text "PE8" at 15.86,40.42 h1.7
  text "PD5" at 66.93,40.04 h1.7
  text "PD6" at 72.58,39.88 h1.7
  text "PE9" at 11.36,37.89 h1.7
  text "PE10" at 15.86,37.875 h1.7
  text "PD3" at 66.93,37.45 h1.7
  text "PD4" at 72.58,37.3 h1.7
  text "PE11" at 11.36,35.345 h1.7
  text "PE12" at 15.86,35.329 h1.7
  text "PD1" at 66.93,34.96 h1.7
  text "PD2" at 72.58,34.82 h1.7
  text "PE13" at 11.36,32.8 h1.7
  text "PE14" at 15.86,32.783 h1.7
  text "PC12" at 66.93,32.27 h1.7
  text "PD0" at 72.58,32.23 h1.7
  text "PE15" at 11.36,30.256 h1.7
  text "PB10" at 15.86,30.237 h1.7
  text "PC11" at 72.22,29.69 h1.7
  text "PC10" at 66.93,29.62 h1.7
  text "PB11" at 11.36,27.711 h1.7
  text "GND" at 15.86,27.691 h1.7
  text "PA14" at 66.93,27.39 h1.7
  text "PA15" at 72.22,27.35 h1.7
  text "VDD" at 11.36,25.167 h1.7
  text "PB12" at 15.86,25.145 h1.7
  text "GND" at 66.93,24.87 h1.7
  text "VDD" at 72.58,24.88 h1.7
  text "PB13" at 11.36,22.622 h1.7
  text "PB14" at 15.86,22.599 h1.7
  text "NC" at 72.58,22.32 h1.7
  text "PA13" at 66.93,22.1 h1.7
  text "PB15" at 11.36,20.078 h1.7
  text "PD8" at 15.86,20.053 h1.7
  text "NC" at 72.58,19.679 h1.7
  text "PC7" at 66.93,19.53 h1.7
  text "PD9" at 11.36,17.533 h1.7
  text "PD10" at 15.86,17.507 h1.7
  text "PC9" at 66.93,16.99 h1.7
  text "PC8" at 72.58,16.993 h1.7
  text "PD11" at 11.36,14.988 h1.7
  text "PD12" at 15.86,14.961 h1.7
  text "PA9" at 66.93,14.59 h1.7
  text "PA8" at 72.58,14.54 h1.7
  text "APM32F407VG" at 53.558,13.702 h2
  text "PD13" at 11.36,12.444 h1.7
  text "PD14" at 15.86,12.415 h1.7
  text "NC" at 66.93,12.19 h1.7
  text "MINIBOARD V1.0" at 57.16,12.18 h1.2
  text "PA10" at 72.27,12.06 h1.7
  text "PD15" at 11.36,9.899 h1.7
  text "PC6" at 15.86,9.869 h1.7
  text "VDD" at 66.81,9.775 h1.7
  text "GND" at 72.32,9.6 h1.7
  text "KEY1" at 16.04,0.615 h1.5
  text "KEY2" at 27.28,0.585 h1.5
  text "RESET" at 64.6,0.5 h1.5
